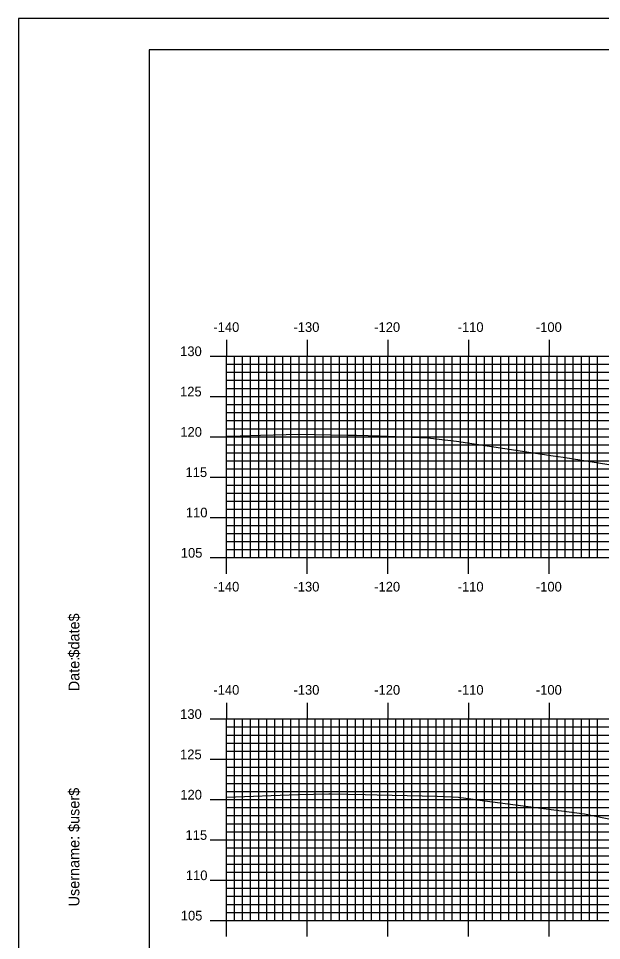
# Model space of a CAD drawing. Extents: x 844143 to 844486, y 363538 to 363758.
# Drawn here: x 844142.7 to 844215, y 363643.2 to 363757.6 of the extents above; entities that cross this region are included whole.
import ezdxf

# ---------------------------------------------------------------- set-up
doc = ezdxf.new("R2010")
doc.units = 0
for name, color, linetype in [('BORDER', 7, 'Continuous'), ('H_V ANNOTATION', 7, 'Continuous'), ('M_Roadway_Centerline', 7, 'Continuous'), ('MAJOR', 7, 'Continuous'), ('MINOR', 7, 'Continuous'), ('PLOT BOUNDARY', 7, 'Continuous'), ('S_Roadway_Centerline', 7, 'Continuous')]:
    doc.layers.add(name, color=color, linetype=linetype)

msp = doc.modelspace()

# ---------------------------------------------------------------- linework, layer by layer
at = {"layer": 'BORDER'}
msp.add_lwpolyline([(844158.85, 363543.72), (844478.85, 363543.72), (844478.85, 363753.72), (844158.85, 363753.72)], close=True, dxfattribs=at)
at = {"layer": 'MAJOR'}
for p, q in [((844168.45, 363717.73), (844168.45, 363715.72)), ((844178.45, 363717.73), (844178.45, 363715.72)), ((844188.45, 363717.73), (844188.45, 363715.72)), ((844198.45, 363717.73), (844198.45, 363715.72)), ((844208.45, 363717.73), (844208.45, 363715.72)), ((844166.45, 363715.72), (844168.45, 363715.72)), ((844168.45, 363715.72), (844448.45, 363715.72)), ((844168.45, 363690.72), (844168.45, 363715.72)), ((844168.45, 363690.72), (844168.45, 363715.72)), ((844168.45, 363715.72), (844448.45, 363715.72)), ((844178.45, 363690.72), (844178.45, 363715.72)), ((844188.45, 363690.72), (844188.45, 363715.72)), ((844198.45, 363690.72), (844198.45, 363715.72)), ((844208.45, 363690.72), (844208.45, 363715.72)), ((844166.45, 363710.72), (844168.45, 363710.72)), ((844168.45, 363710.72), (844448.45, 363710.72)), ((844166.45, 363705.72), (844168.45, 363705.72)), ((844168.45, 363705.72), (844448.45, 363705.72)), ((844166.45, 363700.72), (844168.45, 363700.72)), ((844168.45, 363700.72), (844448.45, 363700.72)), ((844166.45, 363695.72), (844168.45, 363695.72)), ((844168.45, 363695.72), (844448.45, 363695.72)), ((844166.45, 363690.72), (844168.45, 363690.72)), ((844168.45, 363690.72), (844448.45, 363690.72)), ((844168.45, 363690.72), (844448.45, 363690.72)), ((844168.45, 363688.72), (844168.45, 363690.72)), ((844178.45, 363688.72), (844178.45, 363690.72)), ((844188.45, 363688.72), (844188.45, 363690.72)), ((844198.45, 363688.72), (844198.45, 363690.72)), ((844208.45, 363688.72), (844208.45, 363690.72)), ((844168.45, 363672.73), (844168.45, 363670.72)), ((844178.45, 363672.73), (844178.45, 363670.72)), ((844188.45, 363672.73), (844188.45, 363670.72)), ((844198.45, 363672.73), (844198.45, 363670.72)), ((844208.45, 363672.73), (844208.45, 363670.72)), ((844166.45, 363670.72), (844168.45, 363670.72)), ((844168.45, 363670.72), (844448.45, 363670.72)), ((844168.45, 363645.72), (844168.45, 363670.72)), ((844168.45, 363645.72), (844168.45, 363670.72)), ((844168.45, 363670.72), (844448.45, 363670.72)), ((844178.45, 363645.72), (844178.45, 363670.72)), ((844188.45, 363645.72), (844188.45, 363670.72)), ((844198.45, 363645.72), (844198.45, 363670.72)), ((844208.45, 363645.72), (844208.45, 363670.72)), ((844166.45, 363665.72), (844168.45, 363665.72)), ((844168.45, 363665.72), (844448.45, 363665.72)), ((844166.45, 363660.72), (844168.45, 363660.72)), ((844168.45, 363660.72), (844448.45, 363660.72)), ((844166.45, 363655.72), (844168.45, 363655.72)), ((844168.45, 363655.72), (844448.45, 363655.72)), ((844166.45, 363650.72), (844168.45, 363650.72)), ((844168.45, 363650.72), (844448.45, 363650.72)), ((844166.45, 363645.72), (844168.45, 363645.72)), ((844168.45, 363645.72), (844448.45, 363645.72)), ((844168.45, 363645.72), (844448.45, 363645.72)), ((844168.45, 363643.72), (844168.45, 363645.72)), ((844178.45, 363643.72), (844178.45, 363645.72)), ((844188.45, 363643.72), (844188.45, 363645.72)), ((844198.45, 363643.72), (844198.45, 363645.72)), ((844208.45, 363643.72), (844208.45, 363645.72))]:
    msp.add_line(p, q, dxfattribs=at)
at = {"layer": 'MINOR'}
for p, q in [((844169.45, 363690.72), (844169.45, 363715.72)), ((844170.45, 363690.72), (844170.45, 363715.72)), ((844171.45, 363690.72), (844171.45, 363715.72)), ((844172.45, 363690.72), (844172.45, 363715.72)), ((844173.45, 363690.72), (844173.45, 363715.72)), ((844174.45, 363690.72), (844174.45, 363715.72)), ((844175.45, 363690.72), (844175.45, 363715.72)), ((844176.45, 363690.72), (844176.45, 363715.72)), ((844177.45, 363690.72), (844177.45, 363715.72)), ((844179.45, 363690.72), (844179.45, 363715.72)), ((844180.45, 363690.72), (844180.45, 363715.72)), ((844181.45, 363690.72), (844181.45, 363715.72)), ((844182.45, 363690.72), (844182.45, 363715.72)), ((844183.45, 363690.72), (844183.45, 363715.72)), ((844184.45, 363690.72), (844184.45, 363715.72)), ((844185.45, 363690.72), (844185.45, 363715.72)), ((844186.45, 363690.72), (844186.45, 363715.72)), ((844187.45, 363690.72), (844187.45, 363715.72)), ((844189.45, 363690.72), (844189.45, 363715.72)), ((844190.45, 363690.72), (844190.45, 363715.72)), ((844191.45, 363690.72), (844191.45, 363715.72)), ((844192.45, 363690.72), (844192.45, 363715.72)), ((844193.45, 363690.72), (844193.45, 363715.72)), ((844194.45, 363690.72), (844194.45, 363715.72)), ((844195.45, 363690.72), (844195.45, 363715.72)), ((844196.45, 363690.72), (844196.45, 363715.72)), ((844197.45, 363690.72), (844197.45, 363715.72)), ((844199.45, 363690.72), (844199.45, 363715.72)), ((844200.45, 363690.72), (844200.45, 363715.72)), ((844201.45, 363690.72), (844201.45, 363715.72)), ((844202.45, 363690.72), (844202.45, 363715.72)), ((844203.45, 363690.72), (844203.45, 363715.72)), ((844204.45, 363690.72), (844204.45, 363715.72)), ((844205.45, 363690.72), (844205.45, 363715.72)), ((844206.45, 363690.72), (844206.45, 363715.72)), ((844207.45, 363690.72), (844207.45, 363715.72)), ((844209.45, 363690.72), (844209.45, 363715.72)), ((844210.45, 363690.72), (844210.45, 363715.72)), ((844211.45, 363690.72), (844211.45, 363715.72)), ((844212.45, 363690.72), (844212.45, 363715.72)), ((844213.45, 363690.72), (844213.45, 363715.72)), ((844214.45, 363690.72), (844214.45, 363715.72)), ((844168.45, 363714.72), (844448.45, 363714.72)), ((844168.45, 363714.72), (844170.45, 363714.72)), ((844168.45, 363713.72), (844448.45, 363713.72)), ((844168.45, 363713.72), (844170.45, 363713.72)), ((844168.45, 363712.72), (844448.45, 363712.72)), ((844168.45, 363712.72), (844170.45, 363712.72)), ((844168.45, 363711.72), (844448.45, 363711.72)), ((844168.45, 363711.72), (844170.45, 363711.72)), ((844168.45, 363709.72), (844448.45, 363709.72)), ((844168.45, 363709.72), (844170.45, 363709.72)), ((844168.45, 363708.72), (844448.45, 363708.72)), ((844168.45, 363708.72), (844170.45, 363708.72)), ((844168.45, 363707.72), (844448.45, 363707.72)), ((844168.45, 363707.72), (844170.45, 363707.72)), ((844168.45, 363706.72), (844448.45, 363706.72)), ((844168.45, 363706.72), (844170.45, 363706.72)), ((844168.45, 363704.72), (844448.45, 363704.72)), ((844168.45, 363704.72), (844170.45, 363704.72)), ((844168.45, 363703.72), (844448.45, 363703.72)), ((844168.45, 363703.72), (844170.45, 363703.72)), ((844168.45, 363702.72), (844448.45, 363702.72)), ((844168.45, 363702.72), (844170.45, 363702.72)), ((844168.45, 363701.72), (844448.45, 363701.72)), ((844168.45, 363701.72), (844170.45, 363701.72)), ((844168.45, 363699.72), (844448.45, 363699.72)), ((844168.45, 363699.72), (844170.45, 363699.72)), ((844168.45, 363698.72), (844448.45, 363698.72)), ((844168.45, 363698.72), (844170.45, 363698.72)), ((844168.45, 363697.72), (844448.45, 363697.72)), ((844168.45, 363697.72), (844170.45, 363697.72)), ((844168.45, 363696.72), (844448.45, 363696.72)), ((844168.45, 363696.72), (844170.45, 363696.72)), ((844168.45, 363694.72), (844448.45, 363694.72)), ((844168.45, 363694.72), (844170.45, 363694.72)), ((844168.45, 363693.72), (844448.45, 363693.72)), ((844168.45, 363693.72), (844170.45, 363693.72)), ((844168.45, 363692.72), (844448.45, 363692.72)), ((844168.45, 363692.72), (844170.45, 363692.72)), ((844168.45, 363691.72), (844448.45, 363691.72)), ((844168.45, 363691.72), (844170.45, 363691.72)), ((844169.45, 363645.72), (844169.45, 363670.72)), ((844170.45, 363645.72), (844170.45, 363670.72)), ((844171.45, 363645.72), (844171.45, 363670.72)), ((844172.45, 363645.72), (844172.45, 363670.72)), ((844173.45, 363645.72), (844173.45, 363670.72)), ((844174.45, 363645.72), (844174.45, 363670.72)), ((844175.45, 363645.72), (844175.45, 363670.72)), ((844176.45, 363645.72), (844176.45, 363670.72)), ((844177.45, 363645.72), (844177.45, 363670.72)), ((844179.45, 363645.72), (844179.45, 363670.72)), ((844180.45, 363645.72), (844180.45, 363670.72)), ((844181.45, 363645.72), (844181.45, 363670.72)), ((844182.45, 363645.72), (844182.45, 363670.72)), ((844183.45, 363645.72), (844183.45, 363670.72)), ((844184.45, 363645.72), (844184.45, 363670.72)), ((844185.45, 363645.72), (844185.45, 363670.72)), ((844186.45, 363645.72), (844186.45, 363670.72)), ((844187.45, 363645.72), (844187.45, 363670.72)), ((844189.45, 363645.72), (844189.45, 363670.72)), ((844190.45, 363645.72), (844190.45, 363670.72)), ((844191.45, 363645.72), (844191.45, 363670.72)), ((844192.45, 363645.72), (844192.45, 363670.72)), ((844193.45, 363645.72), (844193.45, 363670.72)), ((844194.45, 363645.72), (844194.45, 363670.72)), ((844195.45, 363645.72), (844195.45, 363670.72)), ((844196.45, 363645.72), (844196.45, 363670.72)), ((844197.45, 363645.72), (844197.45, 363670.72)), ((844199.45, 363645.72), (844199.45, 363670.72)), ((844200.45, 363645.72), (844200.45, 363670.72)), ((844201.45, 363645.72), (844201.45, 363670.72)), ((844202.45, 363645.72), (844202.45, 363670.72)), ((844203.45, 363645.72), (844203.45, 363670.72)), ((844204.45, 363645.72), (844204.45, 363670.72)), ((844205.45, 363645.72), (844205.45, 363670.72)), ((844206.45, 363645.72), (844206.45, 363670.72)), ((844207.45, 363645.72), (844207.45, 363670.72)), ((844209.45, 363645.72), (844209.45, 363670.72)), ((844210.45, 363645.72), (844210.45, 363670.72)), ((844211.45, 363645.72), (844211.45, 363670.72)), ((844212.45, 363645.72), (844212.45, 363670.72)), ((844213.45, 363645.72), (844213.45, 363670.72)), ((844214.45, 363645.72), (844214.45, 363670.72)), ((844168.45, 363669.72), (844448.45, 363669.72)), ((844168.45, 363669.72), (844170.45, 363669.72)), ((844168.45, 363668.72), (844448.45, 363668.72)), ((844168.45, 363668.72), (844170.45, 363668.72)), ((844168.45, 363667.72), (844448.45, 363667.72)), ((844168.45, 363667.72), (844170.45, 363667.72)), ((844168.45, 363666.72), (844448.45, 363666.72)), ((844168.45, 363666.72), (844170.45, 363666.72)), ((844168.45, 363664.72), (844448.45, 363664.72)), ((844168.45, 363664.72), (844170.45, 363664.72)), ((844168.45, 363663.72), (844448.45, 363663.72)), ((844168.45, 363663.72), (844170.45, 363663.72)), ((844168.45, 363662.72), (844448.45, 363662.72)), ((844168.45, 363662.72), (844170.45, 363662.72)), ((844168.45, 363661.72), (844448.45, 363661.72)), ((844168.45, 363661.72), (844170.45, 363661.72)), ((844168.45, 363659.72), (844448.45, 363659.72)), ((844168.45, 363659.72), (844170.45, 363659.72)), ((844168.45, 363658.72), (844448.45, 363658.72)), ((844168.45, 363658.72), (844170.45, 363658.72)), ((844168.45, 363657.72), (844448.45, 363657.72)), ((844168.45, 363657.72), (844170.45, 363657.72)), ((844168.45, 363656.72), (844448.45, 363656.72)), ((844168.45, 363656.72), (844170.45, 363656.72)), ((844168.45, 363654.72), (844448.45, 363654.72)), ((844168.45, 363654.72), (844170.45, 363654.72)), ((844168.45, 363653.72), (844448.45, 363653.72)), ((844168.45, 363653.72), (844170.45, 363653.72)), ((844168.45, 363652.72), (844448.45, 363652.72)), ((844168.45, 363652.72), (844170.45, 363652.72)), ((844168.45, 363651.72), (844448.45, 363651.72)), ((844168.45, 363651.72), (844170.45, 363651.72)), ((844168.45, 363649.72), (844448.45, 363649.72)), ((844168.45, 363649.72), (844170.45, 363649.72)), ((844168.45, 363648.72), (844448.45, 363648.72)), ((844168.45, 363648.72), (844170.45, 363648.72)), ((844168.45, 363647.72), (844448.45, 363647.72)), ((844168.45, 363647.72), (844170.45, 363647.72)), ((844168.45, 363646.72), (844448.45, 363646.72)), ((844168.45, 363646.72), (844170.45, 363646.72))]:
    msp.add_line(p, q, dxfattribs=at)
at = {"layer": 'PLOT BOUNDARY'}
msp.add_lwpolyline([(844142.66, 363537.6), (844482.66, 363537.6), (844482.66, 363757.6), (844142.66, 363757.6)], close=True, dxfattribs=at)
at = {"layer": 'S_Roadway_Centerline'}
for points in [[(844168.45, 363705.79), (844170.16, 363705.85), (844172.67, 363705.92), (844177.47, 363706.04), (844183.4, 363705.93), (844184.58, 363705.9), (844187.46, 363705.83), (844193.4, 363705.6), (844194.43, 363705.47), (844196.95, 363705.16), (844208.95, 363703.34), (844210.2, 363703.17), (844215.84, 363702.27)], [(844168.45, 363661.02), (844177.36, 363661.33), (844181.14, 363661.41), (844181.34, 363661.43), (844185.63, 363661.35), (844187.12, 363661.3), (844194.56, 363661.12), (844197.21, 363661.02), (844199.03, 363660.76), (844199.21, 363660.73), (844200.49, 363660.55), (844212.84, 363658.95), (844218.03, 363657.89)]]:
    msp.add_lwpolyline(points, dxfattribs=at)

# ---------------------------------------------------------------- texts
at = {"layer": 'BORDER'}
for s, p in [('$date$', (844150.22, 363678.33)), ('Date:', (844150.22, 363674.15)), ('$user$', (844150.22, 363656.7)), ('Username:', (844150.22, 363647.46))]:
    msp.add_text(s, height=1.339, rotation=90, dxfattribs=at).set_placement(p)
at = {"layer": 'H_V ANNOTATION'}
for s, p in [('-140', (844166.83, 363718.72)), ('-130', (844176.76, 363718.72)), ('-120', (844186.77, 363718.72)), ('-110', (844197.11, 363718.72)), ('-100', (844206.81, 363718.72)), ('130', (844162.71, 363715.72)), ('125', (844162.7, 363710.72)), ('120', (844162.73, 363705.72)), ('115', (844163.38, 363700.72)), ('110', (844163.42, 363695.72)), ('105', (844162.79, 363690.72)), ('-140', (844166.83, 363686.52)), ('-130', (844176.76, 363686.52)), ('-120', (844186.77, 363686.52)), ('-110', (844197.11, 363686.52)), ('-100', (844206.81, 363686.52)), ('-140', (844166.83, 363673.72)), ('-130', (844176.76, 363673.72)), ('-120', (844186.77, 363673.72)), ('-110', (844197.11, 363673.72)), ('-100', (844206.81, 363673.72)), ('130', (844162.71, 363670.72)), ('125', (844162.7, 363665.72)), ('120', (844162.73, 363660.72)), ('115', (844163.38, 363655.72)), ('110', (844163.42, 363650.72)), ('105', (844162.79, 363645.72))]:
    msp.add_text(s, height=1.2, dxfattribs=at).set_placement(p)
at = {"layer": 'M_Roadway_Centerline'}
for s, p in [('C', (844177.46, 363706.04)), ('L', (844177.47, 363706.04)), ('C', (844181.34, 363661.43)), ('L', (844181.34, 363661.42))]:
    msp.add_text(s, height=0.0146, dxfattribs=at).set_placement(p)
at = {"layer": 'MAJOR'}
for p in [(844168.44, 363690.72), (844168.44, 363645.72)]:
    msp.add_text('-', height=0.012, dxfattribs=at).set_placement(p)

doc.saveas('drawing.dxf')
